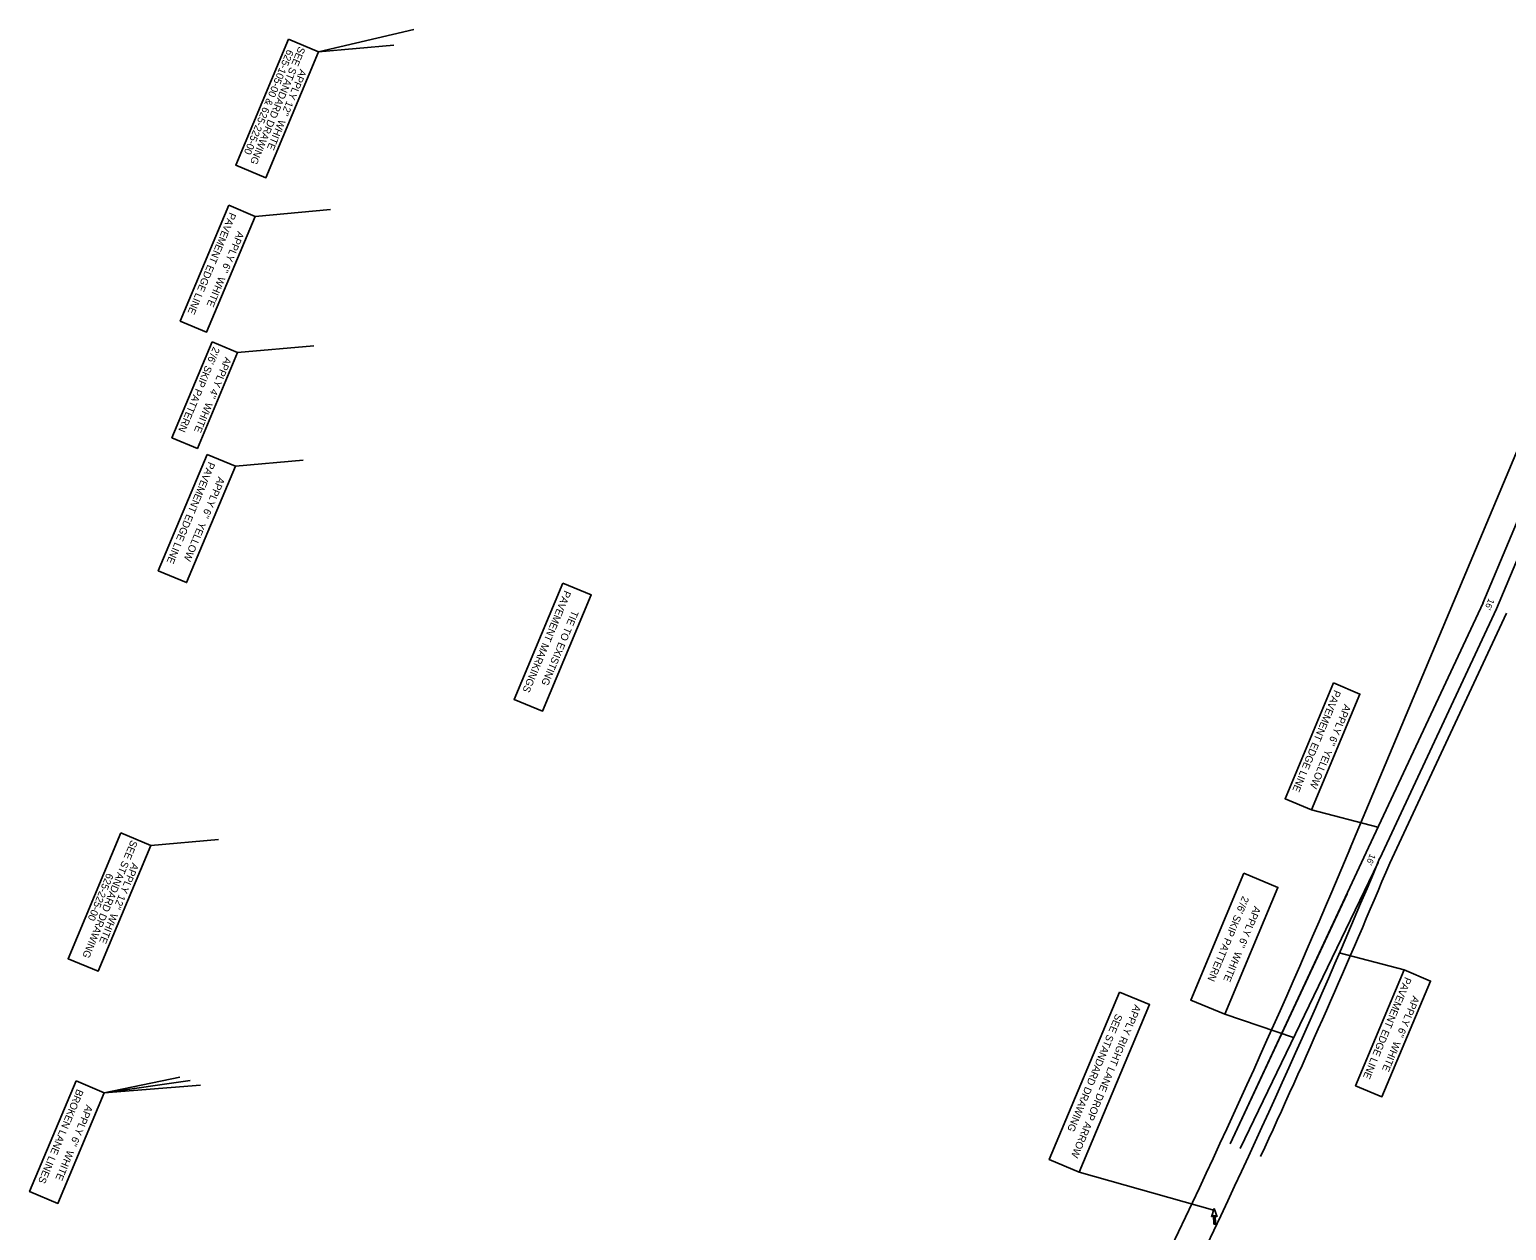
# Model space of a CAD drawing. Extents: x 1966013 to 1974896, y 789499 to 804826.
# Drawn here: x 1967135 to 1968743, y 796189 to 797497 of the extents above; entities that cross this region are included whole.
import ezdxf

# ---------------------------------------------------------------- set-up
doc = ezdxf.new("R2010")
doc.units = 0
for name, color, linetype in [('RD_EX_Conc', 7, 'Continuous'), ('RD_EX_H2O_BlueLn', 7, 'Continuous'), ('RD_HC_Cl', 7, 'Continuous'), ('RD_HC_Data_Rel', 7, 'Continuous'), ('RD_PD_ALT5_CL', 7, 'Continuous'), ('RD_PD_Final_Cl', 7, 'Continuous')]:
    doc.layers.add(name, color=color, linetype=linetype)

msp = doc.modelspace()

# ---------------------------------------------------------------- linework, layer by layer
at = {"layer": 'RD_EX_Conc'}
for p, q in [((1968425, 796212.9), (1968422.4, 796203.8)), ((1968428.3, 796204), (1968425, 796212.9)), ((1968422.4, 796203.8), (1968424.4, 796205.6)), ((1968424.4, 796205.6), (1968424.8, 796196)), ((1968424.8, 796196), (1968426.6, 796196)), ((1968426.6, 796196), (1968426.2, 796205.6)), ((1968426.2, 796205.6), (1968428.3, 796204))]:
    msp.add_line(p, q, dxfattribs=at)
at = {"layer": 'RD_EX_H2O_BlueLn'}
for p, q in [((1967449.9, 797472.7), (1967553.7, 797497.1)), ((1967449.9, 797472.7), (1967531.8, 797480.1)), ((1967380.8, 797293.5), (1967462.7, 797300.9)), ((1967361.7, 797145.2), (1967444.5, 797152.7)), ((1967359.2, 797021.3), (1967433, 797028)), ((1968531.1, 796647.2), (1968603.3, 796628.4)), ((1967267.2, 796608.2), (1967340.9, 796614.9)), ((1968561.2, 796491.3), (1968632, 796472.8)), ((1968436.6, 796424.5), (1968511.7, 796399.3)), ((1967216.5, 796339), (1967298.6, 796356)), ((1967216.5, 796339), (1967310, 796352.2)), ((1967216.5, 796339), (1967321.2, 796347.4)), ((1968278.3, 796252.4), (1968425.8, 796210.6))]:
    msp.add_line(p, q, dxfattribs=at)
for points in [[(1967417.1, 797486.5), (1967359.6, 797349.5), (1967392.4, 797335.7), (1967449.9, 797472.7)], [(1967352, 797305.6), (1967299.2, 797179.5), (1967327.9, 797167.5), (1967380.8, 797293.5)], [(1967333.9, 797156.9), (1967290.1, 797052.4), (1967317.8, 797040.8), (1967361.7, 797145.2)], [(1967328.4, 797034.3), (1967275.2, 796907.6), (1967306.1, 796894.6), (1967359.2, 797021.3)], [(1967715.9, 796894.2), (1967662.8, 796767.5), (1967693.6, 796754.6), (1967746.8, 796881.2)], [(1968555.2, 796785.3), (1968502.3, 796659.3), (1968531.1, 796647.2), (1968583.9, 796773.3)], [(1967234.4, 796622), (1967177, 796485), (1967209.7, 796471.3), (1967267.2, 796608.2)], [(1968457.6, 796578.1), (1968399.7, 796440), (1968436.6, 796424.5), (1968494.5, 796562.7)], [(1968632, 796472.8), (1968579.2, 796346.7), (1968607.9, 796334.7), (1968660.8, 796460.7)], [(1968322, 796448.7), (1968245.5, 796266.1), (1968278.3, 796252.4), (1968354.8, 796435)], [(1967185.7, 796352), (1967135.1, 796231.3), (1967165.9, 796218.4), (1967216.5, 796339)]]:
    msp.add_lwpolyline(points, close=True, dxfattribs=at)
at = {"layer": 'RD_HC_Cl'}
for p, q in [((1968940.8, 797481.5), (1968572.3, 796603)), ((1968616.4, 796589.2), (1968743.5, 796861.2))]:
    msp.add_line(p, q, dxfattribs=at)
for radius, start, end in [(9698, 333.93129, 337.27075), (9744, 335.2169, 337.27133)]:
    msp.add_arc((1959629, 800353.9), radius, start, end, dxfattribs=at)
at = {"layer": 'RD_HC_Data_Rel'}
msp.add_line((1968603.6, 796589.8), (1968453.3, 796278.3), dxfattribs=at)
at = {"layer": 'RD_PD_ALT5_CL'}
for p, q in [((1968717.7, 796872.2), (1968856.4, 797202.9)), ((1968732.5, 796866), (1968871.2, 797196.7)), ((1968590.8, 796600.5), (1968718, 796872.8)), ((1968605.4, 796594), (1968732.5, 796866)), ((1968590.8, 796600.5), (1968442.4, 796283.3)), ((1968569.9, 796555.8), (1968442.4, 796283.3))]:
    msp.add_line(p, q, dxfattribs=at)
msp.add_arc((1959629, 800353.9), 9732, 333.93129, 337.27276, dxfattribs=at)

# ---------------------------------------------------------------- texts
at = {"layer": 'RD_EX_H2O_BlueLn'}
for s, height, rotation, p in [('SEE STANDARD DRAWING', 8, 247.246, (1967428.3, 797479.2)), ('625-105-00 & 625-225-00', 8, 247.246, (1967415.7, 797475.9)), ("APPLY 12''  WHITE", 8, 247.246, (1967429.7, 797454.4)), ('PAVEMENT EDGE LINE', 8, 247.246, (1967353, 797298.5)), ("APPLY 6''  WHITE", 8, 247.246, (1967361.7, 797278)), ("2'/6' SKIP PATTERN", 7.999, 247.2462, (1967335.2, 797152)), ("APPLY 4''  WHITE", 7.999, 247.2462, (1967348, 797141)), ('PAVEMENT EDGE LINE', 8, 247.246, (1967330.1, 797026.8)), ("APPLY 6''  YELLOW", 8, 247.246, (1967340.7, 797010.5)), ('PAVEMENT MARKINGS', 8, 247.246, (1967717.7, 796886.7)), ('TIE TO EXISTING', 8, 247.246, (1967725.9, 796865)), ('PAVEMENT EDGE LINE', 8, 247.246, (1968556.1, 796778.3)), ("APPLY 6''  YELLOW", 8, 247.246, (1968567, 796762.8)), ('SEE STANDARD DRAWING', 8, 247.246, (1967245.7, 796614.8)), ('625-225-00', 8, 247.246, (1967219.4, 796578.8)), ("APPLY 12''  WHITE", 8, 247.246, (1967247, 796590)), ("2'/6' SKIP PATTERN", 7.999, 247.2553, (1968456.1, 796553.8)), ("APPLY 6''  WHITE", 7.999, 247.2553, (1968468.9, 796542.9)), ('PAVEMENT EDGE LINE', 8, 247.246, (1968633, 796465.7)), ('APPLY RIGHT LANE DROP ARROW', 8, 247.2551, (1968338.5, 796435.7)), ("APPLY 6''  WHITE", 8, 247.246, (1968641.7, 796445.1)), ('SEE STANDARD DRAWING', 8, 247.2551, (1968318.2, 796425.7)), ('BROKEN LANE LINES', 8, 247.246, (1967186.8, 796343.6)), ("APPLY 6''  WHITE", 8, 247.246, (1967197, 796326.5))]:
    msp.add_text(s, height=height, rotation=rotation, dxfattribs=at).set_placement(p)
at = {"layer": 'RD_PD_Final_Cl'}
for p in [(1968724.2, 796877.9), (1968595, 796599.9)]:
    msp.add_text("16'", height=7, rotation=247.2476, dxfattribs=at).set_placement(p)

doc.saveas('drawing.dxf')
